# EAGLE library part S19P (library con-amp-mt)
AMP MT CONNECTOR
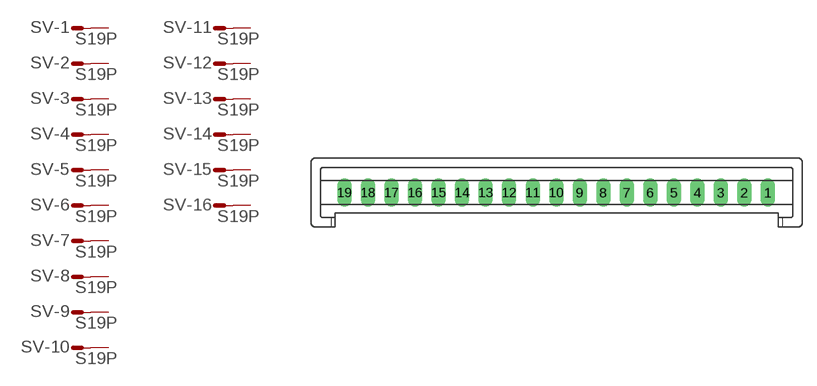
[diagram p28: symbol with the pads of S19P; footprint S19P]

Designator prefix SV; gates -1=M -2=M -3=M -4=M -5=M -6=M -7=M -8=M -9=M -10=M -11=M -12=M -13=M -14=M -15=M -16=M -17=M -18=M -19=M

## S19P (OC_FARNELL: unknown; OC_NEWARK: unknown)  [S19P]
1  -1:S  pas
2  -2:S  pas
3  -3:S  pas
4  -4:S  pas
5  -5:S  pas
6  -6:S  pas
7  -7:S  pas
8  -8:S  pas
9  -9:S  pas
10  -10:S  pas
11  -11:S  pas
12  -12:S  pas
13  -13:S  pas
14  -14:S  pas
15  -15:S  pas
16  -16:S  pas
17  -17:S  pas
18  -18:S  pas
19  -19:S  pas

## Footprint S19P (pad centres in mm)
AMP MT CONNECTOR
drill 1.016 long: 1 22.5,0; 2 20,0; 3 17.5,0; 4 15,0; 5 12.5,0; 6 10,0; 7 7.5,0; 8 5,0; 9 2.5,0; 10 0,0; 11 -2.5,0; 12 -5,0; 13 -7.5,0; 14 -10,0; 15 -12.5,0; 16 -15,0; 17 -17.5,0; 18 -20,0; 19 -22.5,0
